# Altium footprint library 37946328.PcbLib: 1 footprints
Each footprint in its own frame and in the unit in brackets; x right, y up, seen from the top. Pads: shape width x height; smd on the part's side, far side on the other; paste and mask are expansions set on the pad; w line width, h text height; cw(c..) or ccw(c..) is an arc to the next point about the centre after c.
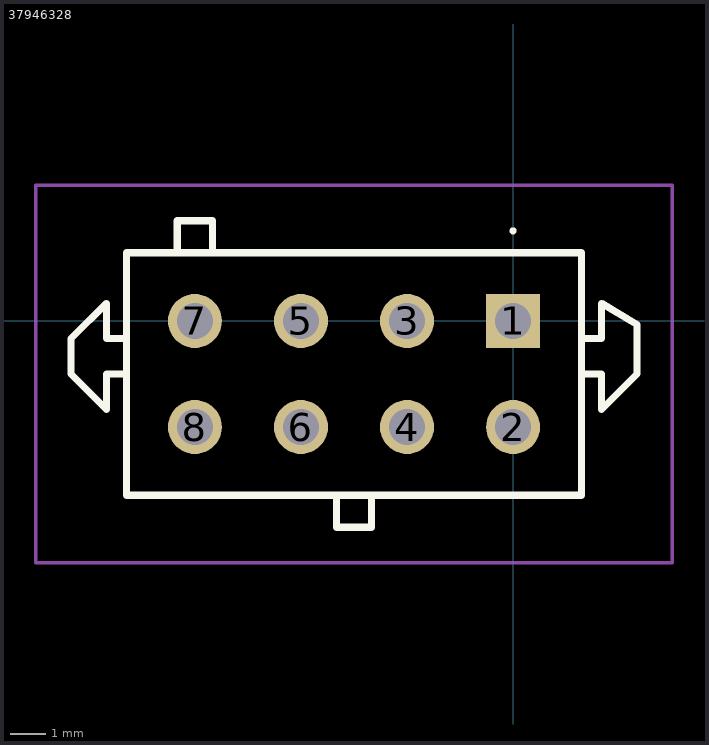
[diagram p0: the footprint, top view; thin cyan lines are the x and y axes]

## 37946328 [mm]
pads (8):
  rect 1.53x1.53 hole 1.02: 1(0,0)
  round 1.53 hole 1.02: 2(0,-3) 3(-3,0) 4(-3,-3) 5(-6,0) 6(-6,-3) 7(-9,0) 8(-9,-3)
Top Overlay:
  lines w0.1: 0,2.5 0,2.5 ; 0,2.5 ccw(c0,2.55) 0,2.6 ; 0,2.5 cw(c0,2.55) 0,2.6 ; 0,2.6 0,2.6
  lines w0.2: -10.93,-1.5 -11.5,-1.5 -11.5,-2.5 -12.5,-1.5 -12.5,-0.5 -11.5,0.5 -11.5,-0.5 -10.93,-0.5 ; -9.5,1.93 -9.5,2.835 -8.5,2.835 -8.5,1.93 ; -5,-4.93 -5,-5.835 -4,-5.835 -4,-4.93 ; 1.93,-1.5 2.5,-1.5 2.5,-2.5 3.5,-1.5 3.5,-0.1 2.5,0.5 2.5,-0.5 1.93,-0.5 ; -10.93,-4.93 1.93,-4.93 1.93,1.93 -10.93,1.93 -10.93,-4.93
Mechanical 15:
  lines w0.1: -10.93,-1.5 -11.5,-1.5 -11.5,-2.5 -12.5,-1.5 -12.5,-0.5 -11.5,0.5 -11.5,-0.5 -10.93,-0.5 ; -9.5,1.93 -9.5,2.835 -8.5,2.835 -8.5,1.93 ; -5,-4.93 -5,-5.835 -4,-5.835 -4,-4.93 ; 1.93,-1.5 2.5,-1.5 2.5,-2.5 3.5,-1.5 3.5,-0.1 2.5,0.5 2.5,-0.5 1.93,-0.5 ; -10.93,-4.93 1.93,-4.93 1.93,1.93 -10.93,1.93 -10.93,-4.93
Mechanical 20:
  lines w0.1: -13.5,-6.835 4.5,-6.835 4.5,3.835 -13.5,3.835 -13.5,-6.835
